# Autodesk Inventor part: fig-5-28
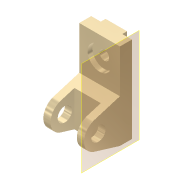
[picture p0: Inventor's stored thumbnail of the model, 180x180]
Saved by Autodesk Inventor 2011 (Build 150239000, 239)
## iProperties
Shininess: 65.0
Angle Display Precision: 2
Document Length Units: 11269
Document Angle Units: 11279
Document Time Units: 11290
Document Mass Units: 11283
Document Length Units Precision: 3
Document Angle Units Precision: 2
Created: 2001-11
Part Number: fig-5-28
Document SubType Name: Modeling
Designer: Renu Muthoo
Density: 1 g/cm^3
Density: 0.0
Volumn: 0.0
Area: 0.0
PropertySet Name: Model Information
Control State: 0
Master: False
Checked Out: False
Author: Renu Muthoo
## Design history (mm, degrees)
node "Sketch1"
sketch "Sketch2"
  geometry: L1 (33.257, 104.664)-(33.257, -75.336); L2 (33.257, -75.336)-(8.257, -75.336); L3 (8.257, -75.336)-(-45.451, -59.045); L4 (-45.451, -1.628)-(8.257, 14.664); L5 (8.257, 14.664)-(8.257, 104.664); L6 (8.257, 104.664)-(33.257, 104.664); C1 r 15 at (-36.743, -30.336); A1 r 30 centre (-36.743, -30.336) between (-45.451, -1.628) and (-45.451, -59.045)
  constraints: 12 end point, 2 centre point, 2 equal length, 2 parallel, 2 point on circle, 2 tangent, 1 coincident, 1 perpendicular, 1 vertical
  dimensions: "d0" = 180 distance of L1.start L1.end; "d1" = 30 radius of A1; "d2" = 25 distance of L5.end L1.start; "d3" = 45 distance from line of L2 A1.centre; "d4" = 70 distance from line of L1 A1.centre; "d5" = 30 diameter of C1
extrude "Extrusion1" new body sketch "Sketch2" distance "d6" = 85; taper "d7" = 0 deg
workplane "Work Plane1"
sketch "Sketch3"
  geometry: L1 (15, 62.364)-(70, 62.364); L2 (70, 62.364)-(70, -52.386); L3 (70, -52.386)-(15, -52.386); L4 (15, -52.386)-(15, 62.364); L5 (0, -45)-(0, -28.708) reference
  constraints: 8 end point, 2 parallel, 1 horizontal, 1 perpendicular
  dimensions: "d8" = 55 distance of L1.start L1.end; "d9" = 15 distance between parallel lines of L5 L4
extrude "Extrusion2" cut sketch "Sketch3" distance "d10" = 50; taper "d11" = 0 deg
sketch "Sketch4"
  geometry: L1 (0, 25)-(85, 25) reference; L2 (0, 0)-(0, 25) reference; L3 (20, 25)-(65, 25); L4 (65, 25)-(65, 35); L5 (65, 35)-(20, 35); L6 (20, 35)-(20, 25)
  constraints: 8 end point, 2 parallel, 1 horizontal, 1 perpendicular, 1 point on line
  dimensions: "d12" = 45 distance of L4.end L5.end; "d13" = 10 distance of L3.end L4.end; "d14" = 20 distance between parallel lines of L2 L6
extrude "Extrusion3" join sketch "Sketch4" stored distance "d15" = 50; taper "d16" = 0 deg
sketch "Sketch5"
  geometry: L1 (85, 0)-(85, 90) reference; L2 (0, 90)-(85, 90) reference; 1 further point
  dimensions: "d17" = 42 distance from line of L2 point (42.5, 48); "d18" = 42.5 distance from line of L1 point (42.5, 48)
hole "Hole1" sketch "Sketch5" at (42.5, 48) diameter "d19" = 20; stored, may be unused: countersink angle "d23" = 82 deg, drill point angle "d25" = 118 deg; dims "d20" = 6, "d21" = 50, "d22" = 10, "d24" = 8
workplane "Work Plane4"
body "Solid1"
other parameters: "d26" = 0
